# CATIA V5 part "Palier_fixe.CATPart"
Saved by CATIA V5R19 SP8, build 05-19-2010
Part number: Palier_fixe
Bounding box of the stored display mesh (mm): x -50 to 50, y -50 to 50, z 0 to 60
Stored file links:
  G:\EU_thinkMotion\CFAO_2010\MMS_groupe1\MMS_groupe1\OK\vduret\vduret\CATIA\Palier_fixe.CATPart
  G:\EU_thinkMotion\CFAO_2010\MMS_groupe1\MMS_groupe1\OK\vduret\vduret\CATIA\Axe.CATPart
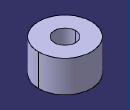
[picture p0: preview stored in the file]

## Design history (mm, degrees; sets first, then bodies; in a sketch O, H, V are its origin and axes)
Body1 (main body)
  Sketch1 on xy-plane, origin (0, 0, 0), H (1, 0, 0), V (0, 1, 0)
    circle A1 centre (0, 0) radius 50
    radius A1 = 50
  Pad1: profile Sketch1, direction (0, 0, 1), length 60
  Sketch2 on start face of Pad1, origin (0, 0, 0), H (1, 0, 0), V (0, -1, 0)
    circle A1 centre (-25, 25) radius 7
    point P1 (-25, 25)
    circle A2 centre (25, 25) radius 7
    circle A3 centre (25, -25) radius 7
    circle A4 centre (-25, -25) radius 7
    radius A1 = 7
    distance H P1 = 25
    distance P1 V = 25
    symmetry: A1 A2 V, A2 A3 H, A1 A4 H
  Pocket1: profile Sketch2, direction (0, 0, 1), length 25
  Sketch3 on start face of Pad1, origin (0, 0, 0), H (1, 0, 0), V (0, -1, 0)
    circle A1 centre (0, 0) radius 20
    radius A1 = 20
  Pocket2: profile Sketch3, direction (0, 0, 1), through (limit type 6)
